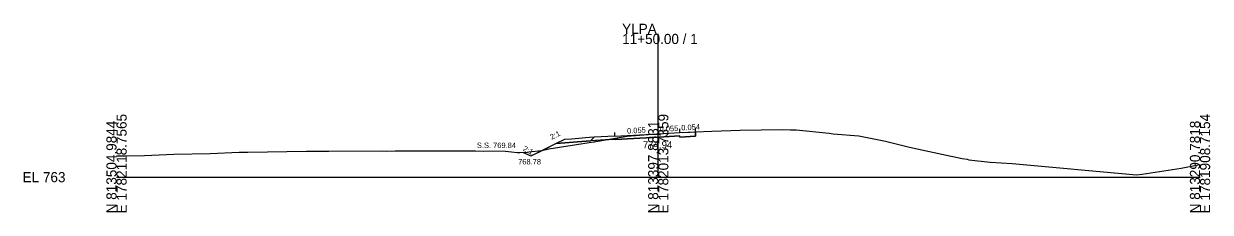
# Model space of a CAD drawing. Extents: x -76 to 1303, y -10 to 9544.
# Drawn here: x -25.7 to 302.8, y 1490.3 to 1542.4 of the extents above; entities that cross this region are included whole.
import ezdxf

# ---------------------------------------------------------------- set-up
doc = ezdxf.new("R2010")
doc.units = 0
for name, color, linetype in [('Exist Cross Section Cell', 7, 'Continuous'), ('Exist XS Center Line Elevation Label', 7, 'Continuous'), ('Exist XS Ground Line', 7, 'Continuous'), ('Prop XS Ditch Standard Text', 7, 'Continuous'), ('Prop XS Dump Level', 7, 'Continuous'), ('Prop XS Earthwork Shape', 7, 'Continuous'), ('Prop XS EOT Tick Mark', 7, 'Continuous'), ('Prop XS Finish Grade', 7, 'Continuous'), ('Prop XS Finish Grade Earthwork', 7, 'Continuous'), ('Prop XS Finish Grade Paved Shoulder', 7, 'Continuous'), ('Prop XS Finish Grade Pavement', 7, 'Continuous'), ('Prop XS Pvmt Edge Slope', 7, 'Continuous'), ('Prop XS SE Text', 7, 'Continuous'), ('Prop XS Side Slope Text', 7, 'Continuous'), ('Prop XS SS Elevation Text', 7, 'Continuous'), ('Prop XS Subgrade Earthwork', 7, 'Continuous'), ('Scratch_Level_3', 7, 'Continuous')]:
    doc.layers.add(name, color=color, linetype=linetype)

msp = doc.modelspace()

# ---------------------------------------------------------------- linework, layer by layer
at = {"layer": 'Exist Cross Section Cell'}
for p, q in [((150, 1500), (150, 1539.6)), ((0, 1500), (150, 1500)), ((150, 1500), (300, 1500))]:
    msp.add_line(p, q, dxfattribs=at)
at = {"layer": 'Exist XS Ground Line'}
for p, q in [((132.71, 1509.82), (141.38, 1511.34)), ((141.38, 1511.34), (146.02, 1511.66)), ((146.02, 1511.66), (147.18, 1511.8)), ((147.18, 1511.8), (149.16, 1511.89)), ((149.16, 1511.89), (150, 1511.94)), ((150, 1511.94), (155.97, 1512.31)), ((155.97, 1512.31), (158.81, 1512.47)), ((158.81, 1512.47), (160.29, 1512.56)), ((160.29, 1512.56), (164.87, 1512.7)), ((164.87, 1512.7), (172.65, 1512.95)), ((172.65, 1512.95), (178.47, 1513.08)), ((178.47, 1513.08), (184.33, 1513.2)), ((184.33, 1513.2), (186.65, 1513.1)), ((186.65, 1513.1), (188.17, 1513.04)), ((188.17, 1513.04), (197.35, 1512.12)), ((197.35, 1512.12), (198.4, 1512.01)), ((198.4, 1512.01), (205.51, 1511.38)), ((205.51, 1511.38), (212.95, 1509.92)), ((119.72, 1507.84), (132.06, 1509.72)), ((132.06, 1509.72), (132.38, 1509.76)), ((132.38, 1509.76), (132.71, 1509.82)), ((212.95, 1509.92), (215.09, 1509.38)), ((215.09, 1509.38), (219.53, 1508.28)), ((219.53, 1508.28), (228.55, 1506.32)), ((0, 1505.94), (2.38, 1505.88)), ((2.38, 1505.88), (7.78, 1505.97)), ((7.78, 1505.97), (15.91, 1506.39)), ((15.91, 1506.39), (25.94, 1506.55)), ((25.94, 1506.55), (33.94, 1506.89)), ((33.94, 1506.89), (34.99, 1506.89)), ((34.99, 1506.89), (36.38, 1506.93)), ((36.38, 1506.93), (52.62, 1507.16)), ((52.62, 1507.16), (53.56, 1507.16)), ((53.56, 1507.16), (58.8, 1507.18)), ((58.8, 1507.18), (73.7, 1507.28)), ((73.7, 1507.28), (74.73, 1507.23)), ((74.73, 1507.23), (77.11, 1507.25)), ((77.11, 1507.25), (79.72, 1507.28)), ((79.72, 1507.28), (99.42, 1507.28)), ((99.42, 1507.28), (101.65, 1507.2)), ((101.65, 1507.2), (103.34, 1507.26)), ((103.34, 1507.26), (107.67, 1507.23)), ((107.67, 1507.23), (109.34, 1506.99)), ((109.34, 1506.99), (110.94, 1506.78)), ((110.94, 1506.78), (111.68, 1506.78)), ((111.68, 1506.78), (113.82, 1506.91)), ((113.82, 1506.91), (114.17, 1506.96)), ((114.17, 1506.96), (117.72, 1507.4)), ((117.72, 1507.4), (119.72, 1507.84)), ((228.55, 1506.32), (234.14, 1505.18)), ((234.14, 1505.18), (235.52, 1504.93)), ((235.52, 1504.93), (236.02, 1504.79)), ((236.02, 1504.79), (241.92, 1504.12)), ((241.92, 1504.12), (247.95, 1503.82)), ((247.95, 1503.82), (282.38, 1500.64)), ((283.98, 1500.85), (294.79, 1502.49)), ((294.79, 1502.49), (299.46, 1503.41)), ((299.46, 1503.41), (300, 1503.53)), ((282.38, 1500.64), (283.98, 1500.85))]:
    msp.add_line(p, q, dxfattribs=at)
at = {"layer": 'Prop XS Dump Level'}
for p, q in [((138, 1511.35), (150, 1512)), ((150, 1512), (156, 1512.33))]:
    msp.add_line(p, q, dxfattribs=at)
at = {"layer": 'Prop XS Earthwork Shape'}
for points in [[(156, 1511.08), (156, 1511.41), (150.05, 1511.09), (138.05, 1510.43), (135.36, 1510.29), (141.38, 1511.34), (146.02, 1511.66), (147.18, 1511.8), (149.16, 1511.89), (150, 1511.94), (155.97, 1512.31), (158.81, 1512.47), (160.29, 1512.56), (160.29, 1511.31)], [(121.75, 1509.3), (118.13, 1507.49), (119.72, 1507.84), (132.06, 1509.72), (132.38, 1509.76), (132.71, 1509.82), (135.36, 1510.29), (131.25, 1510.06)], [(114.71, 1505.78), (112.61, 1506.84), (113.82, 1506.91), (114.17, 1506.96), (117.72, 1507.4), (118.13, 1507.49)]]:
    msp.add_lwpolyline(points, close=True, dxfattribs=at)
at = {"layer": 'Prop XS EOT Tick Mark'}
for p, q in [((138, 1511.35), (138, 1512.35)), ((156, 1512.33), (156, 1513.33)), ((160.29, 1512.56), (160.29, 1513.56))]:
    msp.add_line(p, q, dxfattribs=at)
at = {"layer": 'Prop XS Finish Grade'}
for p, q in [((124, 1510.43), (121.75, 1509.3)), ((126, 1510.53), (124, 1510.43)), ((131, 1510.93), (126, 1510.53)), ((132.22, 1511.03), (131, 1510.93))]:
    msp.add_line(p, q, dxfattribs=at)
at = {"layer": 'Prop XS Finish Grade Earthwork'}
for p, q in [((121.75, 1509.3), (114.71, 1505.78)), ((114.71, 1505.78), (112.61, 1506.84))]:
    msp.add_line(p, q, dxfattribs=at)
at = {"layer": 'Prop XS Finish Grade Paved Shoulder'}
for p, q in [((138, 1511.35), (132.22, 1511.03)), ((156, 1512.33), (160.29, 1512.56))]:
    msp.add_line(p, q, dxfattribs=at)
at = {"layer": 'Prop XS Finish Grade Pavement'}
for p, q in [((138, 1511.35), (150, 1512)), ((150, 1512), (156, 1512.33))]:
    msp.add_line(p, q, dxfattribs=at)
at = {"layer": 'Prop XS Pvmt Edge Slope'}
msp.add_line((132.22, 1511.03), (131.25, 1510.06), dxfattribs=at)
at = {"layer": 'Prop XS Subgrade Earthwork'}
for p, q in [((150.05, 1511.09), (156, 1511.41)), ((156, 1511.08), (156, 1511.41)), ((156, 1511.08), (160.29, 1511.31)), ((160.29, 1511.31), (160.29, 1512.56)), ((131.25, 1510.06), (121.75, 1509.3)), ((138.05, 1510.43), (131.25, 1510.06)), ((138.05, 1510.43), (150.05, 1511.09))]:
    msp.add_line(p, q, dxfattribs=at)
at = {"layer": 'Scratch_Level_3'}
for p, q in [((124, 1510.43), (121.75, 1509.3)), ((121.75, 1509.3), (131.25, 1510.06)), ((126, 1510.53), (124, 1510.43)), ((131, 1510.93), (126, 1510.53)), ((132.22, 1511.03), (131, 1510.93)), ((131.25, 1510.06), (132.22, 1511.03))]:
    msp.add_line(p, q, dxfattribs=at)

# ---------------------------------------------------------------- texts
at = {"layer": 'Exist Cross Section Cell'}
for s, p in [('YLPA', (140, 1539.6)), ('11+50.00 / 1', (140, 1536.8)), ('EL 763', (-26, 1498.6))]:
    msp.add_text(s, height=2.8, dxfattribs=at).set_placement(p)
for s, p in [('N 813504.9844', (0, 1490)), ('E 1782118.7565', (2.8, 1490)), ('N 813397.8831', (150, 1490)), ('E 1782013.7359', (152.8, 1490)), ('N 813290.7818', (300, 1490)), ('E 1781908.7154', (302.8, 1490))]:
    msp.add_text(s, height=2.8, rotation=90, dxfattribs=at).set_placement(p)
at = {"layer": 'Exist XS Center Line Elevation Label'}
msp.add_text('774.94', height=2, dxfattribs=at).set_placement((145.72, 1507.94))
at = {"layer": 'Prop XS Ditch Standard Text'}
msp.add_text('768.78', height=1.5, dxfattribs=at).set_placement((111.2, 1503.52))
at = {"layer": 'Prop XS Dump Level'}
msp.add_text('Case4', height=0.04, dxfattribs=at).set_placement((126, 1510.45))
at = {"layer": 'Prop XS SE Text'}
for s, p in [('0.054', (156.41, 1512.9)), ('0.055', (141.4, 1512.03)), ('0.055', (150.4, 1512.52))]:
    msp.add_text(s, height=1.5, rotation=3.1213, dxfattribs=at).set_placement(p)
at = {"layer": 'Prop XS Side Slope Text'}
for rotation, p in [(26.5651, (120.48, 1510.3)), (333.4349, (112.38, 1507.43))]:
    msp.add_text('2:1', height=1.5, rotation=rotation, dxfattribs=at).set_placement(p)
at = {"layer": 'Prop XS SS Elevation Text'}
msp.add_text('S.S. 769.84', height=1.5, dxfattribs=at).set_placement((99.78, 1508.05))

doc.saveas('drawing.dxf')
